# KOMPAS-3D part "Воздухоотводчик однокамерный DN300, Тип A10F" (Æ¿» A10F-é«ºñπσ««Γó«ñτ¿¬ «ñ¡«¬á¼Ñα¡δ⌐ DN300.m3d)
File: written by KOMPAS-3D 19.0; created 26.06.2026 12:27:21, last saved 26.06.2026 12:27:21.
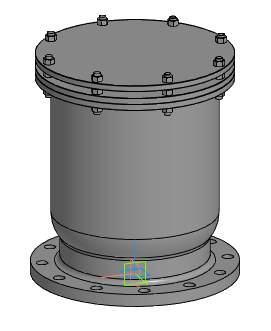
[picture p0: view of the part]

Document properties: Автор: Энергия; Полное имя файла: Z:\3.Личные\kachalov\001_3d для проектировщиков\х.х Тип A10F Воздухоотводчик однокамерный фланцевый\_step\Тип A10F-Воздухоотводчик однокамерный DN300.m3d

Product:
- Part/product: Воздухоотводчик однокамерный DN300  | designation Тип A10F

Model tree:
1. Операция без истории:1  (labels: Тип A10F; Воздухоотводчик однокамерный DN300)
